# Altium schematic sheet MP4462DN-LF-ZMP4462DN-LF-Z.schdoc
size 127 x 101 mm
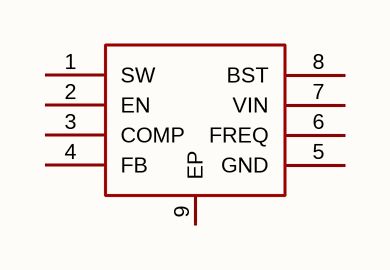
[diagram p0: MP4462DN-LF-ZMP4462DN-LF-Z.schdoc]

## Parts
U?  mp4462dn-lf-z  [SOIC-8_L5.0-W4.0-P1.27-LS6.0-BL-EP2.0]  (value not drawn)

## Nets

Not connected (* = marked no-connect by the designer): U? 1(SW) 2(EN) 3(COMP) 4(FB) 5(GND) 6(FREQ) 7(VIN) 8(BST) 9(EP)

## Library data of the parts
U? = mp4462dn-lf-z: 功能类型:降压型;工作电压:3.8V~36V;输出电压:800mV~30V;输出电流:3.5A;输出类型:可调;; Manufacturer: MPS(芯源); AddInBom: yes; ModelId: d3dfb165ce8644e793b750cd6f375e75; ModelTransform: 192.913,236.22,0,0,0,0,0,0,0; Function: 降压型; Output Current: 3.5A; Frequency - Switching: 2MHz；4MHz; Synchronous Rectifier: 否; Number of Outputs: 1; Topology: 降压式; Quiescent Current: 120uA; Switch tube (built-in/external): 内置; Output Type: 可调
